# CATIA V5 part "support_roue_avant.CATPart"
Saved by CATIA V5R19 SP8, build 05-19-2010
Part number: support_roue_avant
Bounding box of the stored display mesh (mm): x 0 to 70, y -33.166 to 40, z -87.798 to 20
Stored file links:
  U:\Thinkmotion\Assemblage final\support_roue_avant.CATPart
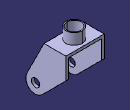
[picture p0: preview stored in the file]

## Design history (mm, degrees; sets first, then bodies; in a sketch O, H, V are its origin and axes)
Mirror1: of the body so far, about face of Pad3
Sketch1 on yz-plane, origin (0, 0, 0), H (0, 1, 0), V (0, 0, 1)
  line L1 (0, 0) -> (40, 0)
  line L2 (40, 0) -> (40, -38.9737)
  line L3 (40, -38.9737) -> (-3.8032, -82.7769)
  line L4 (-31.4317, -62.8634) -> (0, 0)
  arc A1 centre (-16.0017, -70.5784) radius 17.2513 from (-31.4317, -62.8634) to (-3.8032, -82.7769) ccw
  length L1 = 40
  horizontal: L1 H
  vertical: L2 V
  tangency: A1 L4, A1 L3
Pad1: profile Sketch1, direction (1, 0, 0), length 5
Body1 (main body)
  Sketch2 on end face of Pad1, origin (5, 0, 0), H (0, 1, 0), V (0, 0, 1)
    line L1 (0, 0) -> (40, 0)
    line L2 (40, 0) -> (40, -5)
    line L3 (40, -5) -> (0, -5)
    line L4 (0, -5) -> (0, 0)
    reference projected line E1 (40, -38.9737) -> (40, 0) from edge [face of Pad1 from Sketch1.L2 | end face of Pad1]
    length L2 = 5
    horizontal: L1 H, L3 H
    vertical: L2 V, L4 V
    coincidence: L2 E1, L4 V
  Pad2: profile Sketch2, direction (1, 0, 0), length 30
  Sketch3 on face of Pad2, origin (0, 0, 0), H (1, 0, 0), V (0, 1, 0)
    arc A1 centre (35, 20) radius 15 from (35, 35) to (35, 5) ccw
    point P1 (35, 20)
    reference projected line E1 (35, 40) -> (35, 0) from edge [face of Pad2 | end face of Pad2]
    reference intersected line E2 through (0, 0) direction (-1, 0) from zx-plane
    reference projected line E3 (0, 40) -> (5, 40) from edge [face of Pad2 | face of Pad2]
    point P2 (63.7228, 0)
    arc A2 centre (35, 20) radius 13 from (35, 33) to (35, 7) ccw
    line L1 (35, 35) -> (35, 33)
    point P5 (35, 7)
    line L2 (35, 7) -> (35, 5)
    distance A2 A1 = 2
    radius A1 = 15
    coincidence: E1 P1, P2 H, L1 P5, L1 L2
    equidistance: E2 E3 P1
    vertical: L1 V, L2 V
  Pad3: profile Sketch3, direction (0, 0, 1), length 20
  Sketch4 on face of Mirror1, origin (70, -15.435, -69.2596), H (0, 1, 0), V (0, 0, 1)
    point P1 (0, 0)
  Hole1: placed by Sketch4, at (70, -15.435, -69.2596) direction (-1, 0, 0), diameter 15, through (limit type 3)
